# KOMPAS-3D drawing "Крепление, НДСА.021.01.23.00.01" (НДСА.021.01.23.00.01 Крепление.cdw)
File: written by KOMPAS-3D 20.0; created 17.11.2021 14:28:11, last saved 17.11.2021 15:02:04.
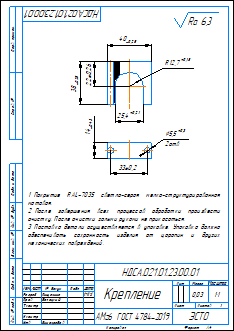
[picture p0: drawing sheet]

Sheet 1: A4, portrait

Document properties: Параметр неуказанной шероховатости: Ra 6,3; 340675408472: <item xmlns="http://appius.ru/pdm" xmlns:xs="http://www.w3.org/2001/XMLSchema" xmlns:xsi="http://www.w3.org/2001/XMLSchema-instance" xsi:type="item">  <element xmlns:d2p1="http://v8.1c.ru/8.1/data/enterprise/current-config" xsi:type="d2p1:CatalogRef.aps_Элемен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; 340675408672: <item xmlns="http://appius.ru/pdm" xmlns:xs="http://www.w3.org/2001/XMLSchema" xmlns:xsi="http://www.w3.org/2001/XMLSchema-instance" xsi:type="item">  <element xmlns:d2p1="http://v8.1c.ru/8.1/data/enterprise/current-config" xsi:type="d2p1:CatalogRef.aps_Элемен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; 251524470605: <item xmlns="http://appius.ru/pdm" xmlns:xs="http://www.w3.org/2001/XMLSchema" xmlns:xsi="http://www.w3.org/2001/XMLSchema-instance" xsi:type="item">  <element xmlns:d2p1="http://v8.1c.ru/8.1/data/enterprise/current-config" xsi:type="d2p1:CatalogRef.aps_Элемен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; PLM_CDWXDTO: <item xmlns="http://appius.ru/pdm" xmlns:xs="http://www.w3.org/2001/XMLSchema" xmlns:xsi="http://www.w3.org/2001/XMLSchema-instance" xsi:type="item">  <element xmlns:d2p1="http://v8.1c.ru/8.1/data/enterprise/current-config" xsi:type="d2p1:CatalogRef.aps_Элемен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; Масса: 0.0270278; PDM_DOCXDTO: <item xmlns="http://appius.ru/pdm" xmlns:xs="http://www.w3.org/2001/XMLSchema" xmlns:xsi="http://www.w3.org/2001/XMLSchema-instance" xsi:type="item">  <element xmlns:d2p1="http://v8.1c.ru/8.1/data/enterprise/current-config" xsi:type="d2p1:CatalogRef.aps_Элемен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; PDM_ITEMXDTO: <item xmlns="http://appius.ru/pdm" xmlns:xs="http://www.w3.org/2001/XMLSchema" xmlns:xsi="http://www.w3.org/2001/XMLSchema-instance" xsi:type="item">  <element xmlns:d2p1="http://v8.1c.ru/8.1/data/enterprise/current-config" xsi:type="d2p1:CatalogRef.aps_Элемен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

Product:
- Part/product: Крепление  | designation НДСА.021.01.23.00.01
    Материал: АМг6  ГОСТ 4784-2019 (density 2640 kg/m3)
    Масса: 0.0270278
    additional columns: <item xmlns="http://appius.ru/pdm" xmlns:xs="http://www.w3.org/2001/XMLSchema" x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; <item xmlns="http://appius.ru/pdm" xmlns:xs="http://www.w3.org/2001/XMLSchema" x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; <item xmlns="http://appius.ru/pdm" xmlns:xs="http://www.w3.org/2001/XMLSchema" x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; <item xmlns="http://appius.ru/pdm" xmlns:xs="http://www.w3.org/2001/XMLSchema" x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; <item xmlns="http://appius.ru/pdm" xmlns:xs="http://www.w3.org/2001/XMLSchema" x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
    source file: НДСА.021.01.23.00.01 Крепление.cdw

Title block, sheet 1: Наименование: Крепление; designation: НДСА.021.01.23.00.01; Материал: АМг6  ГОСТ 4784-2019; Масса: 0,03; Количество листов документа: 1; organisation: ЭСТО; Форматы листов документа: A4; stored path: C:\Users\s.pischagina\Desktop\PLM\НДСА.021.01.23.00.01 Крепление.cdw; Разработал: Пищагина; Проверил: Белецкий; Утвердил: Виноградов; Разработал, date: 17.11.21

Views: Вид 1, Местный разрез 1, Слева, Проекционный вид 2
Referenced files in C:\Users\s.pischagina\Desktop\PLM\: НДСА.021.01.23.00.01 Крепление.m3d
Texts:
  Ra 6,3
  НДСА.021.01.23.00.01 Крепление
Dimensions and other numbers on the sheet: 40; 12,7; 22±0,26; 25,4; 38; 33±0,2; 14; 5,5; 2отв; 1:1; 1; 0,03; 17.11.21

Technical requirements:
  Покрытие RAL-7035 светло-серая мелко-структурированная
  матовая.
  После завершения всех процессов обработки произвести
  очистку. После очистки голыми руками не прикасаться.
  Поставка детали осуществляется в упаковке. Упаковка должна
  обеспечивать сохранность изделия от царапин и других
  механических повреждений.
